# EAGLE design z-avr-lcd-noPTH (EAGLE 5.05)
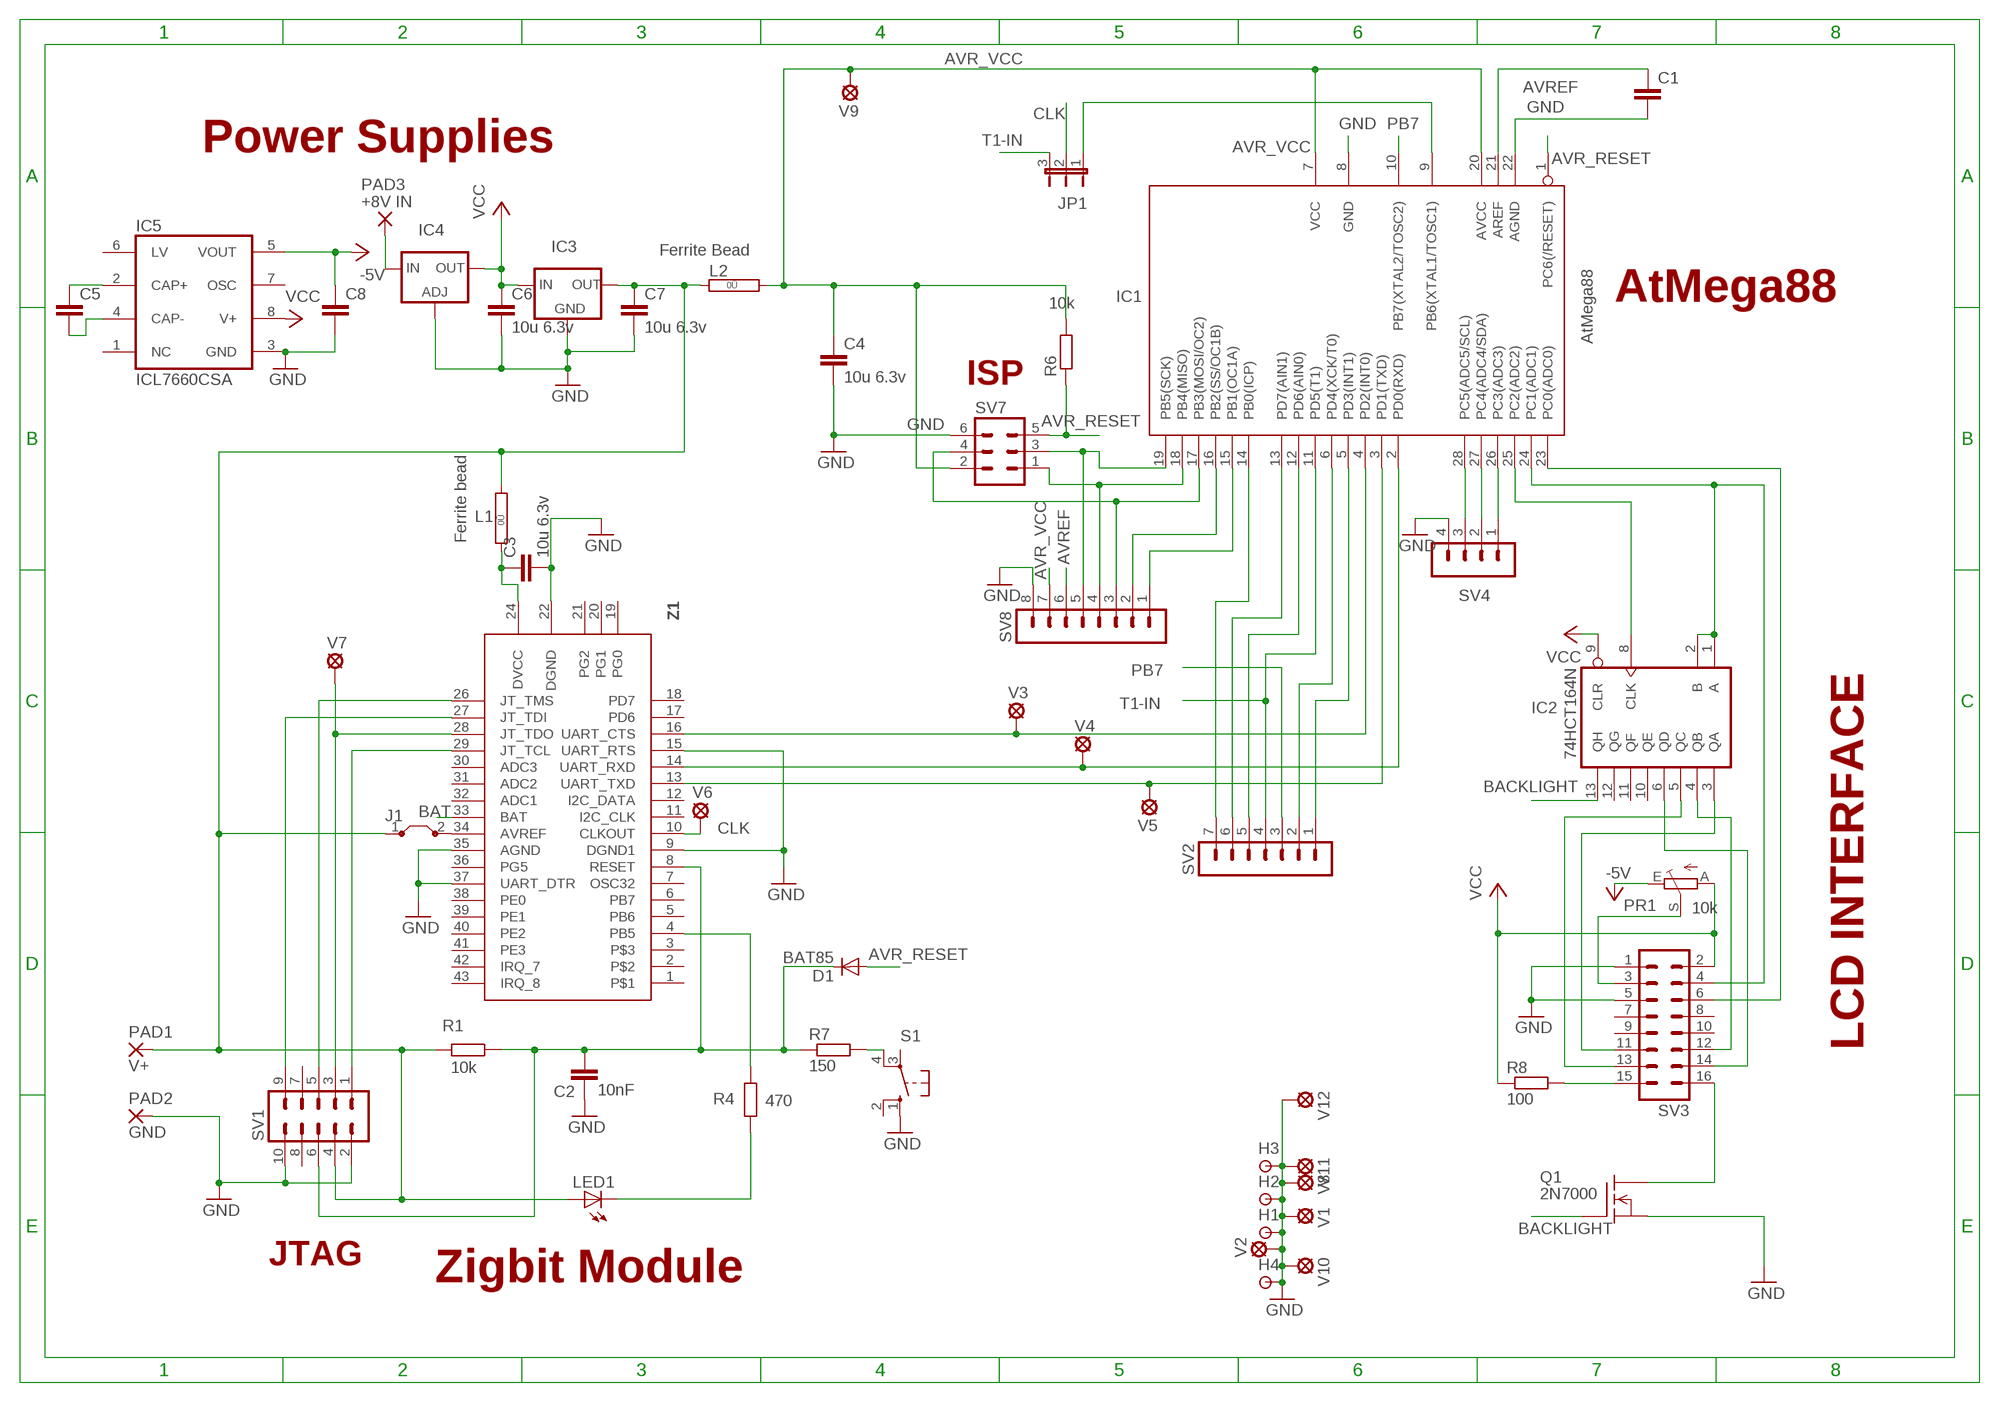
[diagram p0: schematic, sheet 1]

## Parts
C1  C-EUC1206  [C1206]
C2  10nF  C5P  [C050-030-075]
C3  10u 6.3v  C-EUC1206  [C1206]
C4  10u 6.3v  C-EUC1206  [C1206]
C5  C-EUC1206  [C1206]
C6  10u 6.3v  C-EUC1206  [C1206]
C7  10u 6.3v  C-EUC1206  [C1206]
C8  C-EUC1206  [C1206]
D1  BAT85  1N4148  [DO34-7]
H1  HOLE/SMALL  [1,6/0,8]
H2  HOLE/SMALL  [1,6/0,8]
H3  HOLE/SMALL  [1,6/0,8]
H4  HOLE/SMALL  [1,6/0,8]
IC1  AtMega88  MEGA8-P  [DIL28-3]
IC2  74HCT164N  74ACT164N  [DIL14]
IC3  MC1702-3302E/TO 3.3V LDO VREG  XC63FPT  [TO92]
IC4  LD117ADT50TR  [DPACK]
IC5  ICL7660CSA  [SO08]
J1  J7MM  [07]
JP1  3 way Jumper  JP2E  [JP2]
L1  Ferrite bead  0R  [0R/10]
L2  Ferrite Bead  JUMPER_0R  [JUMPER_0R/10]
LED1  3MM red LED  LED-3MM3MM  [HLMP-D105]
PAD1  V+  TERMINAL-PAD  [2,54/1,1]
PAD2  GND  TERMINAL-PAD  [2,54/1,1]
PAD3  +8V IN  PAD-TERMINAL  [2,54/1,1]
PR1  10k  VAR_RESISTOR_TRIMS63P  [S63P]
Q1  2N7000  [TO92]
R1  10k  R  [0207/10]
R4  470  R  [0207/10]
R6  10k  R  [0207/10]
R7  150  R  [0207/10]
R8  100  R  [0207/10]
S1  BW3-1000 PCB pushbutton  10-XX  [B3F-10XX]
SV1  10 way IDC header  ML10  [ML10]
SV2  7 way pin header  MA07-1  [MA07-1]
SV3  16 way IDC mail header  ML16  [ML16]
SV4  4 way pin header  MA04-1  [MA04-1]
SV7  6 pin IDC male header  ML6  [ML6]
SV8  8 way pin header  MA08-1  [MA08-1]
V1  HOLE/VIA  [LSP10]
V2  HOLE-VIA  [LSP10]
V3  HOLE-VIA  [LSP10]
V4  HOLE-VIA  [LSP10]
V5  HOLE-VIA  [LSP10]
V6  HOLE-VIA  [LSP10]
V7  HOLE-VIA  [LSP10]
V8  HOLE-VIA  [LSP10]
V9  HOLE-VIA  [LSP10]
V10  HOLE-VIA  [LSP10]
V11  HOLE-VIA  [LSP10]
V12  HOLE-VIA  [LSP10]
Z1  ZDM-A1281-A2N  [ZIGSMD]

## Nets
-5V: C8.1 IC5.5(VOUT) PR1.E
AVR_RESET: D1.A IC1.1(PC6(/RESET)) R6.1 SV7.5
AVR_VCC [supply]: C4.1 IC1.7(VCC) IC1.20(AVCC) L2.2 R6.2 SV7.2 SV8.7 V9.MP
AVREF: C1.1 IC1.21(AREF) SV8.6
BACKLIGHT: IC2.13(QH) Q1.2(G)
BAT: Z1.33(BAT)
CLK: JP1.2 V6.MP Z1.10(CLKOUT)
GND [supply]: C1.2 C2.1 C3.2 C4.2 C6.2 C7.2 C8.2 H1.1(P) H2.1(P) H3.1(P) H4.1(P) IC1.8(GND) IC1.22(AGND) IC3.1(GND) IC4.1(ADJ) IC5.3(GND) PAD2.1(P) Q1.3(S) S1.1(S) SV1.2 SV1.10 SV3.1 SV3.5 SV4.4 SV7.6 SV8.8 V1.MP V2.MP V8.MP V10.MP V11.MP V12.MP Z1.9(DGND1) Z1.15(UART_RTS) Z1.22(DGND) Z1.35(AGND) Z1.37(UART_DTR)
N$1: IC1.18(PB4(MISO)) SV7.1 SV8.4
N$2: IC1.19(PB5(SCK)) SV7.3 SV8.5
N$3: IC1.24(PC1(ADC1)) IC2.1(A) IC2.2(B) SV3.4
N$4: IC1.25(PC2(ADC2)) IC2.8(CLK)
N$5: IC1.28(PC5(ADC5/SCL)) SV4.3
N$6: R7.2 S1.4(P1)
N$7: IC1.27(PC4(ADC4/SDA)) SV4.2
N$8: IC1.17(PB3(MOSI/OC2)) SV7.4 SV8.3
N$9: SV1.5 Z1.26(JT_TMS)
N$10: SV1.1 Z1.29(JT_TCL)
N$11: SV1.3 V7.MP Z1.28(JT_TDO)
N$12: IC1.26(PC3(ADC3)) SV4.1
N$13: C2.2 D1.C R1.2 R7.1 SV1.6 Z1.8(RESET)
N$14: IC2.6(QD) SV3.14
N$15: IC1.23(PC0(ADC0)) SV3.6
N$16: J1.2 Z1.34(AVREF)
N$17: C5.1 IC5.2(CAP+)
N$18: IC1.4(PD2(INT0)) V3.MP Z1.16(UART_CTS)
N$19: PR1.S SV3.3
N$20: IC1.2(PD0(RXD)) V4.MP Z1.14(UART_RXD)
N$21: IC1.3(PD1(TXD)) V5.MP Z1.13(UART_TXD)
N$22: IC2.3(QA) SV3.11
N$23: IC2.4(QB) SV3.12
N$24: IC2.5(QC) SV3.13
N$25: C5.2 IC5.4(CAP-)
N$26: R8.2 SV3.15
N$27: Q1.1(D) SV3.16
N$28: R4.2 Z1.4(PB5)
N$29 [supply]: IC4.3(IN) PAD3.1(P)
N$30: LED1.K(C) R4.1
N$31: SV1.9 Z1.27(JT_TDI)
N$32: IC1.9(PB6(XTAL1/TOSC1)) JP1.1
N$33 [supply]: C3.1 L1.1 Z1.24(DVCC)
N$34 [supply]: C7.1 IC3.3(OUT) J1.1 L1.2 L2.1 LED1.A PAD1.1(P) R1.1 SV1.4
N$37: IC1.5(PD3(INT1)) SV2.1
N$38: IC1.15(PB1(OC1A)) SV8.1
N$39: IC1.16(PB2(SS/OC1B)) SV8.2
N$40: IC1.12(PD6(AIN0)) SV2.5
N$41: IC1.13(PD7(AIN1)) SV2.6
N$42: IC1.14(PB0(ICP)) SV2.7
N$44: IC1.6(PD4(XCK/T0)) SV2.2
PB7: IC1.10(PB7(XTAL2/TOSC2)) SV2.3
T1-IN: IC1.11(PD5(T1)) JP1.3 SV2.4
VCC [supply]: C6.1 IC2.9(CLR) IC3.2(IN) IC4.4(OUT) IC5.8(V+) PR1.A R8.1 SV3.2
Unconnected: IC2.10(QE) IC2.11(QF) IC2.12(QG) IC5.1(NC) IC5.6(LV) IC5.7(OSC) S1.2(S1) S1.3(P) SV1.7 SV1.8 SV3.7 SV3.8 SV3.9 SV3.10 Z1.1 Z1.2 Z1.3 Z1.5(PB6) Z1.6(PB7) Z1.7(OSC32) Z1.11(I2C_CLK) Z1.12(I2C_DATA) Z1.17(PD6) Z1.18(PD7) Z1.19(PG0) Z1.20(PG1) Z1.21(PG2) Z1.30(ADC3) Z1.31(ADC2) Z1.32(ADC1) Z1.36(PG5) Z1.38(PE0) Z1.39(PE1) Z1.40(PE2) Z1.41(PE3) Z1.42(IRQ_7) Z1.43(IRQ_8)

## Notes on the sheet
- Power Supplies
- AtMega88
- ISP
- LCD INTERFACE
- JTAG
- Zigbit Module

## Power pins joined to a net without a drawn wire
GND: IC2.7(GND)
VCC: IC2.14(VCC)

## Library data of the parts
C1 C3-C8 = rcl:C-EU: CAPACITOR, European symbol
C2 = ee2parts:C: Capacitor
D1 = ee2parts:1N4148: DIODE
H1-H4 = ee2parts:HOLE/SMALL: SMALL THROUGH-HOLE PAD/TESTPOINT
IC1 = atmel:MEGA8-P: MICROCONTROLLER 8 Kbytes FLASH, 1 kbytes SRAM, 512 bytes EEPROM, USART, 4-channel 10 bit ADC, 2-channel 8 bit ADC Pin compatible with Atmega48, ATMega88, ATMega168 Source: avr.lbr
IC2 = 74xx-eu:74*164: 8-bit parallel out SHIFT REGISTER
IC3 = v-reg:XC63FP: Positiv Voltage Regulators www.torex.co.jp/english/product/pro02/pdf/0201_xc62fp.pdf
IC4 = v-reg:LD117A?*: Low drop fixed and adjustable positive voltage regulators 1 A Source: http://www.st.com/stonline/products/literature/ds/7194/ld1117axx.pdf
IC5 = maxim:ICL7660CSA: VOLTAGE CONVERTER
J1 = jumper:J: Bridge
JP1 = jumper:JP2E: JUMPER
L1 = jumper:0R: Bridge 0R 10mm
L2 = z-avr-lcd-noPTH:JUMPER_0R: Bridge 0R 10mm
LED1 = ee2parts:LED-3MM: LED
PAD1 PAD2 = ee2parts:TERMINAL-PAD: LARGE THROUGH-HOLE PAD
PAD3 = ee2parts:PAD-TERMINAL: LARGE THROUGH-HOLE PAD
PR1 = ee2parts:VAR_RESISTOR_TRIM: Variable resistor / potentiometer Trimmer potentiometer - Note that slider to end makes variable resistance
Q1 = z-avr-lcd-noPTH:2N7000: N-Channel Enhancement MOSFET 200V; 0,16A; 11Ohm
R1 R4 R6-R8 = ee2parts:R: Resistor
S1 = switch-omron:10-XX: OMRON SWITCH
SV1 = con-harting-ml:ML10: HARTING
SV2 = con-lstb:MA07-1: PIN HEADER
SV3 = con-ml:ML16: HARTING
SV4 = con-lstb:MA04-1: PIN HEADER
SV7 = con-harting-ml:ML6: HARTING
SV8 = con-lstb:MA08-1: PIN HEADER
V1 = ee2parts:HOLE/VIA: FIXED VIA
V2-V12 = ee2parts:HOLE-VIA: FIXED VIA
Z1 = ee2parts:ZDM-A1281-A2

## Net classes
1 supply: width 0.635 mm

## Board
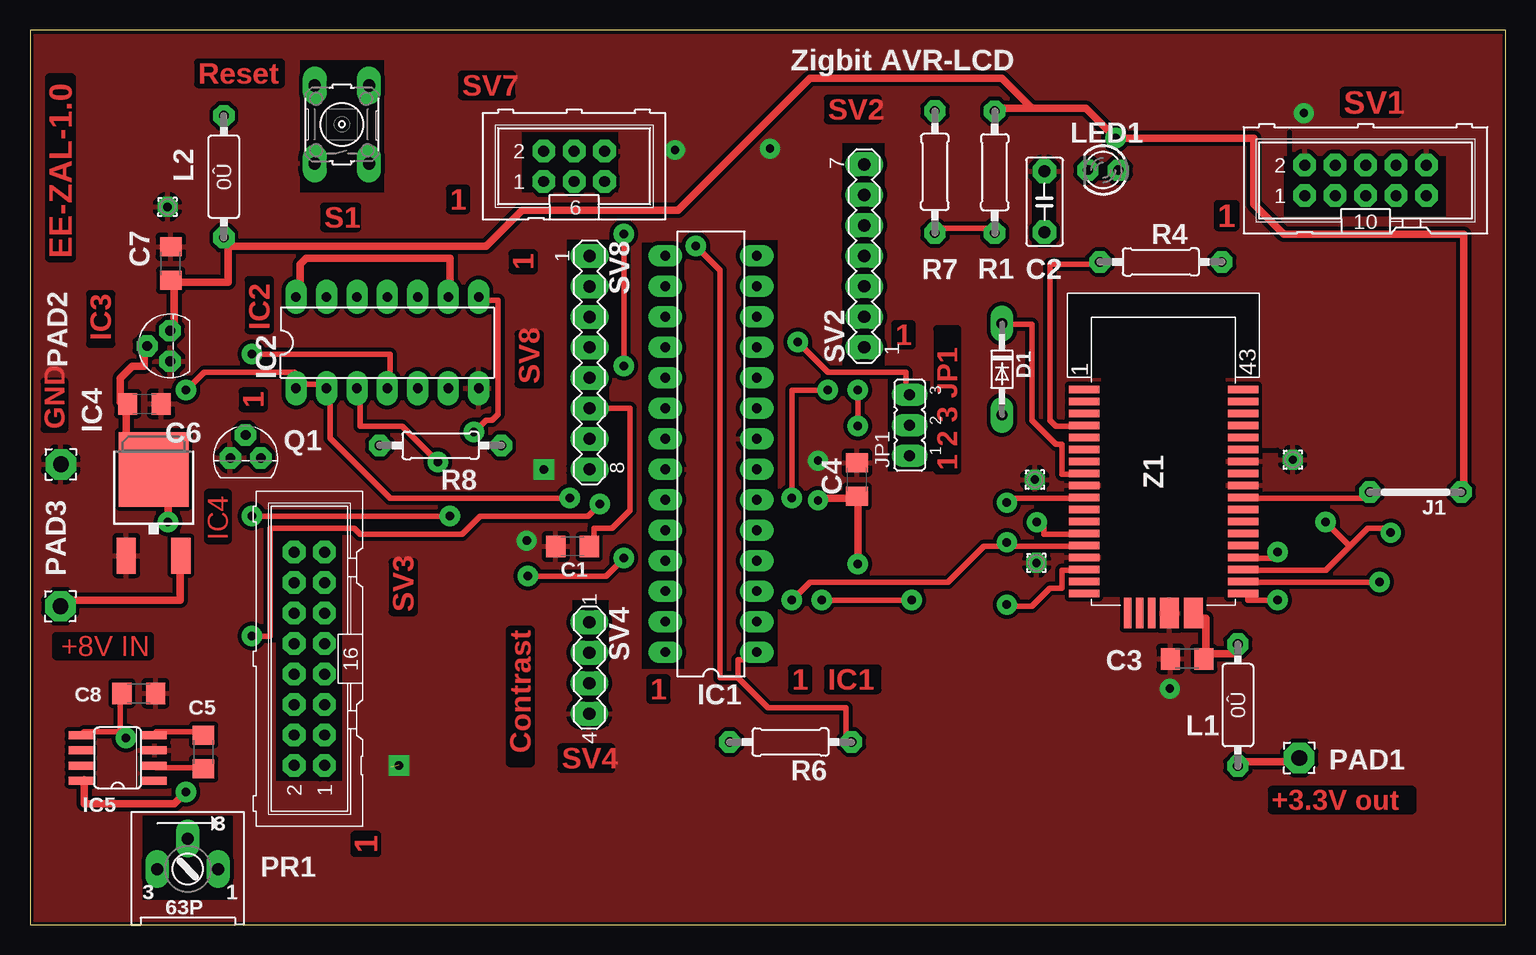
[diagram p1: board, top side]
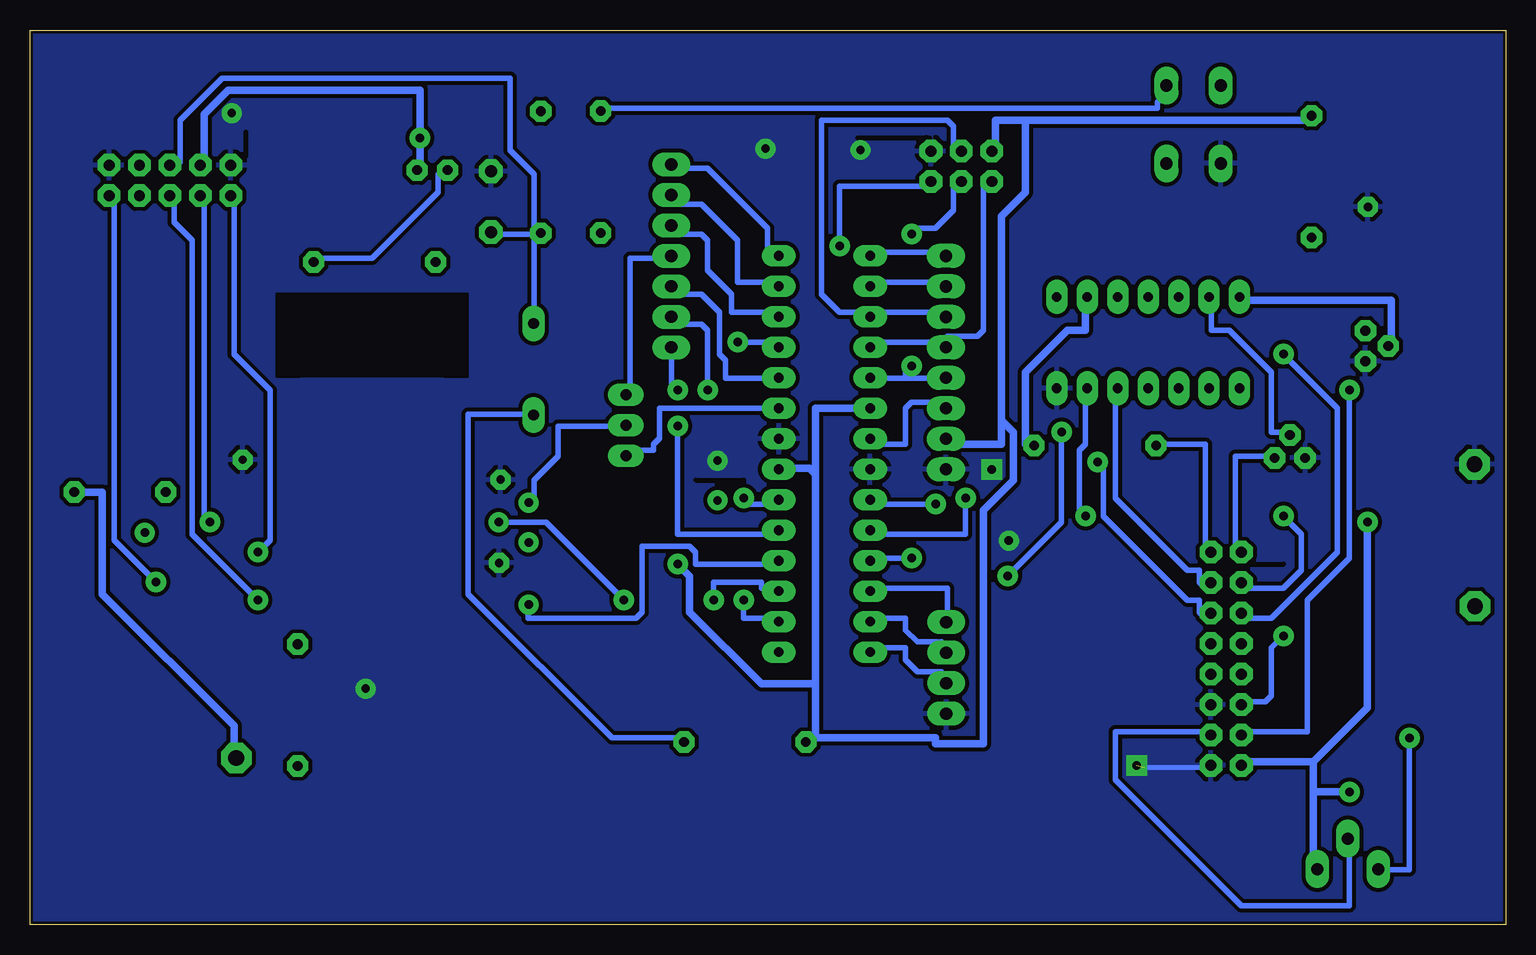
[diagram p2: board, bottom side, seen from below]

Size 123 x 74.58 mm. Coordinates in mm from the lower left corner, seen from the top.
Outline: 0,0 123,0 123,74.58 0,74.58 0,0
Copper layers (1*16): Top 0.035mm / dielectric 1.5mm / Bottom 0.035mm
Design rules "zigbit_rules *": minimum track width 18mil, minimum drill 0.7mm, track to track 13mil, track to pad 13mil, pad to pad 13mil, via to via 13mil, smd to smd 0mil, copper to edge 10mil, drill to drill 10mil, minimum pad ring 19mil, minimum via ring 20mil, stop-mask expansion 0mil, vias tented up to drill 0mil, thermal gap 15mil
tRestrict: area 104.5,59.1 to 118,64.1; area 87.2,62.1 to 91.7,63.6; area 83.5,56.6 to 85.5,63.6; area 41,61.1 to 49,66.1; area 67.7,46.7 to 71.2,65.2; area 22.5,61.1 to 29.5,72.1; area 44.8,36.6 to 48.3,57.1; area 20.5,12 to 26,32.5; area 9.4,2.1 to 16.9,9.1; area 51,21.3 to 54.5,56.8; area 59.3,21.5 to 62.3,57; area 71.5,37.8 to 75,45.3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; 2 lines
bRestrict: 4 lines
vRestrict: area 19.5,8.1 to 29,36.6; area 37,58.6 to 52.5,68.6; area 101,56.6 to 121.5,66.6; area 8.5,-0.2 to 18.7,10

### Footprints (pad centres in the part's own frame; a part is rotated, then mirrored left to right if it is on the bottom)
C1206 = smd 1.6 x 1.8: 1 -1.4,0; 2 1.4,0
C050-030-075 = drill 1 octagon: 1 -2.54,0; 2 2.54,0
DO34-7 = drill 0.9 long: A 3.81,0; C -3.81,0
1,6/0,8 = drill 0.7 pad 1.6 octagon: 1 0,0
DIL28-3 = drill 0.813 long: 1 -16.51,-3.81; 2 -13.97,-3.81; 3 -11.43,-3.81; 4 -8.89,-3.81; 5 -6.35,-3.81; 6 -3.81,-3.81; 7 -1.27,-3.81; 8 1.27,-3.81; 9 3.81,-3.81; 10 6.35,-3.81; 11 8.89,-3.81; 12 11.43,-3.81; 13 13.97,-3.81; 14 16.51,-3.81; 15 16.51,3.81; 16 13.97,3.81; 17 11.43,3.81; 18 8.89,3.81; 19 6.35,3.81; 20 3.81,3.81; 21 1.27,3.81; 22 -1.27,3.81; 23 -3.81,3.81; 24 -6.35,3.81; 25 -8.89,3.81; 26 -11.43,3.81; 27 -13.97,3.81; 28 -16.51,3.81
DIL14 = drill 0.813 long: 1 -7.62,-3.81; 2 -5.08,-3.81; 3 -2.54,-3.81; 4 0,-3.81; 5 2.54,-3.81; 6 5.08,-3.81; 7 7.62,-3.81; 8 7.62,3.81; 9 5.08,3.81; 10 2.54,3.81; 11 0,3.81; 12 -2.54,3.81; 13 -5.08,3.81; 14 -7.62,3.81
TO92 = drill 0.813 octagon: 1 -1.27,0; 2 0,1.905; 3 1.27,0
DPACK = smd 1.6 x 3: 1 -2.28,-4.8; 3 2.28,-4.8 | smd 5.8 x 6.2: 4 0,2.38
SO08 = smd 0.66 x 2.032: 1 -1.905,-3.073; 2 -0.635,-3.073; 3 0.635,-3.073; 4 1.905,-3.073; 5 1.905,3.073; 6 0.635,3.073; 7 -0.635,3.073; 8 -1.905,3.073
07 = drill 0.813 pad 1.6 octagon: 1 -3.81,0; 2 3.81,0
JP2 = drill 0.914 long: 1 -2.54,0; 2 0,0; 3 2.54,0
0R/10 = drill 0.813 pad 1.6 octagon: 1 -5.08,0; 2 5.08,0
JUMPER_0R/10 = drill 0.813 pad 1.6 octagon: 1 -5.08,0; 2 5.08,0
HLMP-D105 = drill 0.8 octagon: A -1.27,0; K 1.27,0
2,54/1,1 = drill 1.3 pad 2.54 octagon: 1 0,0
S63P = drill 1 long: A 2.54,0; E -2.54,0; S 0,2.54
TO92' = drill 0.813 octagon: 1 1.27,0; 2 0,1.905; 3 -1.27,0
0207/10 = drill 0.8 octagon: 1 -5.08,0; 2 5.08,0
B3F-10XX = drill 1.016 long: 1 -3.251,2.261; 2 3.251,2.261; 3 -3.251,-2.261; 4 3.251,-2.261
ML10 = drill 0.914 octagon: 1 -5.08,-1.27; 2 -5.08,1.27; 3 -2.54,-1.27; 4 -2.54,1.27; 5 0,-1.27; 6 0,1.27; 7 2.54,-1.27; 8 2.54,1.27; 9 5.08,-1.27; 10 5.08,1.27
MA07-1 = drill 1.016 long: 1 -7.62,0; 2 -5.08,0; 3 -2.54,0; 4 0,0; 5 2.54,0; 6 5.08,0; 7 7.62,0
ML16 = drill 0.914 octagon: 1 -8.89,-1.27; 2 -8.89,1.27; 3 -6.35,-1.27; 4 -6.35,1.27; 5 -3.81,-1.27; 6 -3.81,1.27; 7 -1.27,-1.27; 8 -1.27,1.27; 9 1.27,-1.27; 10 1.27,1.27; 11 3.81,-1.27; 12 3.81,1.27; 13 6.35,-1.27; 14 6.35,1.27; 15 8.89,-1.27; 16 8.89,1.27
MA04-1 = drill 1.016 long: 1 -3.81,0; 2 -1.27,0; 3 1.27,0; 4 3.81,0
ML6 = drill 0.914 octagon: 1 -2.54,-1.27; 2 -2.54,1.27; 3 0,-1.27; 4 0,1.27; 5 2.54,-1.27; 6 2.54,1.27
MA08-1 = drill 1.016 long: 1 -8.89,0; 2 -6.35,0; 3 -3.81,0; 4 -1.27,0; 5 1.27,0; 6 3.81,0; 7 6.35,0; 8 8.89,0
LSP10 = drill 0.7 pad 1.016 round: MP 0,0
ZIGSMD = smd 0.635 x 2.54: 1 7,6.635; 2 6,6.635; 3 5,6.635; 4 4,6.635; 5 3,6.635; 6 2,6.635; 7 1,6.635; 8 0,6.635; 9 -1,6.635; 10 -2,6.635; 11 -3,6.635; 12 -4,6.635; 13 -5,6.635; 14 -6,6.635; 15 -7,6.635; 16 -8,6.635; 17 -9,6.635; 18 -10,6.635; 26 -10,-6.635; 27 -9,-6.635; 28 -8,-6.635; 29 -7,-6.635; 30 -6,-6.635; 31 -5,-6.635; 32 -4,-6.635; 33 -3,-6.635; 34 -2,-6.635; 35 -1,-6.635; 36 0,-6.635; 37 1,-6.635; 38 2,-6.635; 39 3,-6.635; 40 4,-6.635; 41 5,-6.635; 42 6,-6.635; 43 7,-6.635 | smd 2.54 x 0.635: 19 -11.635,3; 20 -11.635,2; 21 -11.635,1 | smd 2.54 x 1.6: 22 -11.635,-0.5; 24 -11.635,-2.5

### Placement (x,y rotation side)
C1  45.23,31.54 180 top
C2  84.57,60.27 270 top
C3  96.46,22.17 180 top
C4  68.94,37.12 90 top
C5  14.47,14.42 90 top
C6  9.54,43.42 0 top
C7  11.74,55.12 90 top
C8  9.07,19.3 0 top
D1  81.03,46.31 270 top
H1  105.27,38.77 0 top
H2  11.47,59.84 0 top
H3  83.77,37.11 0 top
H4  83.9,30.17 0 top
IC1  56.77,39.25 90 top
IC2  29.79,48.53 0 top
IC3  11.68,48.25 90 top
IC4  10.31,35.58 0 top
IC5  7.31,13.92 90 top
J1  115.5,36.08 180 top
JP1  73.32,41.65 90 top
L1  100.69,18.32 270 top
L2  16.16,62.36 90 top
LED1  89.46,62.9 180 top
PAD1  105.81,13.92 0 top
PAD2  2.58,38.39 90 top
PAD3  2.54,26.56 0 top
PR1  13.15,4.66 0 top
Q1  2N7000  [TO92']  17.97,38.92 0 top
R1  80.42,62.73 270 top
R4  94.27,55.25 180 top
R6  63.4,15.24 180 top
R7  75.43,62.75 90 top
R8  34.22,39.96 180 top
S1  26,66.71 90 top
SV1  111.34,62.05 0 top
SV2  69.55,55.75 90 top
SV3  23.29,22.18 90 top
SV4  46.62,21.42 270 top
SV7  45.36,63.23 0 top
SV8  46.64,46.86 270 top
V1  53.77,64.58 0 top
V2  95.02,19.69 0 top
V3  81.43,26.69 0 top
V4  81.43,31.88 0 top
V5  83.93,33.57 0 top
V6  81.43,35.19 0 top
V7  113.43,32.69 0 top
V8  65.69,38.69 0 top
V9  65.69,35.38 0 top
V10  61.69,64.69 0 top
V11  106.19,67.65 0 top
V12  41.41,32.03 0 top
Z1  94.49,37.62 90 top

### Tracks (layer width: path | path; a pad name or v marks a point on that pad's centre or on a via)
-5V  (via drill 0.7)
  Top 0.457: 7.5,16.08 7.5,19.08 C8.1 | 7.5,16.08 4.5,16.08 IC5.5 | 7.5,16.08 v8,15.58
  Bottom 0.457: v8,15.58 8,4.58 10.5,4.58 PR1.E
AVR_RESET  (via drill 0.7)
  Top 0.457: 59,20.58 61.5,18.08 68,18.08 68,15.58 R6.1 | 59,20.58 59,22.08 59.5,22.08 IC1.1 | v55.5,56.58 57.5,54.58 57.5,20.58 59,20.58
  Bottom 0.457: D1.A 81.5,42.58 86.5,42.58 86.5,27.58 74.5,15.58 68.5,15.58 R6.1 | v55.5,56.58 55.5,61.58 48,61.58 SV7.5
AVR_VCC  (via drill 0.7)
  Top 0.635: V9.MP 66,35.58 68.5,35.58 C4.1 69,35.58 v69,30.08
  Bottom 0.635: 57.5,15.58 58,15.58 R6.2 57.5,15.58 | 57.5,20.08 57.5,37.58 | 57.5,15.58 57.5,20.08 | 57.5,37.58 58,38.08 60.5,38.08 IC1.7 | 57.5,37.58 57.5,43.08 53,43.08 IC1.20 | v69,30.08 68,29.08 68,26.08 62,20.08 57.5,20.08 | 40,67.08 42.5,67.08 42.5,64.58 SV7.2 | 40,67.08 16.5,67.08 L2.2 | 42,42.08 42,59.08 40,61.08 40,67.08 | 42,42.08 42,40.08 46.5,40.08 SV8.7 | 57.5,15.58 47.5,15.58 47.5,15.08 43.5,15.08 43.5,34.58 41,37.08 41,41.08 42,42.08
AVREF
  Top 0.457: C1.1 47,31.58 47,33.08 48.5,33.08 50,34.58 50,43.08 48,43.08 SV8.6
  Bottom 0.457: IC1.21 52.5,40.08 50,40.08 50,43.08 49.5,43.58 47,43.58 47,43.08 SV8.6
BACKLIGHT
  Bottom 0.457: Q1.2 18,41.08 19.5,41.08 19.5,46.08 23,49.58 24.5,49.58 24.5,52.08 IC2.13
CLK
  Top 0.457: Z1.10 87.5,35.58 81.5,35.58 V6.MP
  Bottom 0.457: JP1.2 73.5,41.58 79,41.58 79,39.08 81,37.08 81,35.58 V6.MP
GND  (via drill 0.7)  (1 unrouted)
  Bottom 0.406: 25.32,13.23 25.39,13.16 30.11,13.16
  other vias: 42.83,37.94 30.75,13.3
  pour Bottom: 0,74.08 123,74.08 123,0 0,0
  pour Top: 0,74.08 123,74.08 123,0 0,0
N$1
  Bottom 0.457: IC1.18 52.5,48.58 47,48.58 SV8.4 46.5,48.58 46.5,49.08 44,49.08 43.5,49.58 43.5,61.58 43,61.58 SV7.1
N$2  (via drill 0.7)
  Top 0.457: v49.5,46.58 v49.5,57.58
  Bottom 0.457: 50,45.58 47,45.58 SV8.5 | 50,45.58 52.5,45.58 IC1.19 | v49.5,57.58 49.5,58.08 47.5,58.08 46,59.58 46,61.58 45.5,61.58 SV7.3 | v49.5,46.58 50,46.08 50,45.58
N$3  (via drill 0.7)
  Top 0.457: 23,45.08 24.5,45.08 IC2.2 25,44.58 25,40.58 30,35.58 v45,35.58 | 23,45.08 22.5,45.08 IC2.1 23,45.08 | v13,44.58 14.5,46.08 22,46.08 23,45.08
  Bottom 0.457: v45,35.58 45,32.58 52.5,32.58 IC1.24 | v13,44.58 13,30.58 16.5,27.08 16.5,16.08 22,16.08 SV3.4
N$4  (via drill 0.7)
  Top 0.457: v49.5,30.58 48,29.08 v41.5,29.08 | v37,41.08 38,42.08 38.5,42.08 39,42.58 39,52.08 37.5,52.08 IC2.8
  Bottom 0.457: v49.5,30.58 52.5,30.58 IC1.25 | v41.5,29.08 37,33.58 v37,41.08
N$5
  Bottom 0.457: IC1.28 52.5,23.08 50,23.08 50,22.08 49,21.08 47,21.08 47,20.58 SV4.3
N$6
  Bottom 0.457: R7.2 75,68.08 29,68.08 29,68.58 28.5,69.08 28.5,69.58 S1.4
N$7
  Bottom 0.457: IC1.27 52.5,25.58 50,25.58 50,24.58 49,23.58 47,23.58 47,23.08 SV4.2
N$8
  Bottom 0.457: SV8.3 47,51.08 52.5,51.08 IC1.17 53,51.08 55.5,51.08 57,52.58 57,67.08 46.5,67.08 46,66.58 46,65.08 45.5,64.58 SV7.4
N$9  (via drill 0.7)
  Top 0.457: v104,27.08 101.5,27.08 101.5,27.58 Z1.26
  Bottom 0.457: v104,27.08 109.5,32.58 109.5,57.08 111,58.58 111,60.58 SV1.5
N$10  (via drill 0.7)
  Top 0.457: v104,31.08 103.5,30.58 101.5,30.58 Z1.29
  Bottom 0.457: v104,31.08 103,32.08 103,44.58 106,47.58 106,60.58 SV1.1
N$11  (via drill 0.7)
  Top 0.457: 110,31.58 111.5,33.08 113,33.08 V7.MP | 110,31.58 108,29.58 101.5,29.58 Z1.28 | 110,31.58 v108,33.58
  Bottom 0.457: v108,33.58 108.5,34.08 108.5,60.58 SV1.3
N$12
  Bottom 0.457: IC1.26 52.5,28.08 46.5,28.08 46.5,25.58 SV4.1
N$13
  Top 0.457: Z1.8 87.5,37.58 86,37.58 86,40.08 85.5,40.08 83.5,42.08 83.5,50.08 81.5,50.08 D1.C | R7.1 75.5,58.08 80,58.08 R1.2
  Bottom 0.457: 81,57.58 84.5,57.58 C2.2 | 81,57.58 80.5,57.58 R1.2 81,57.58 | 81,57.58 81,62.58 83,64.58 83,70.58 107,70.58 110.5,67.08 110.5,63.58 111,63.58 SV1.6 | 81,57.58 81,50.58 D1.C
N$14  (via drill 0.7)
  Top 0.457: v35,34.08 v18.5,34.08
  Bottom 0.457: v35,34.08 35.5,34.58 35.5,39.58 35,40.08 35,44.58 IC2.6 | v18.5,34.08 17,32.58 17,29.58 18.5,28.08 22,28.08 SV3.14
N$15  (via drill 0.7)
  Top 0.457: v47.5,35.08 46.5,34.08 37.5,34.08 36,32.58 27.5,32.58 27,33.08 20,33.08 20,24.08 v18.5,24.08
  Bottom 0.457: v47.5,35.08 52.5,35.08 IC1.23 | v18.5,24.08 19.5,23.08 19.5,19.08 20,18.58 22,18.58 SV3.6
N$16
  Top 0.457: Z1.34 101.5,35.58 111.5,35.58 112,36.08 J1.2
N$17
  Top 0.457: C5.1 14,13.08 10.5,13.08 IC5.2
N$18
  Top 0.457: Z1.16 87.5,29.58 86,29.58 86,28.08 85,28.08 83.5,26.58 81.5,26.58 V3.MP
  Bottom 0.457: IC1.4 61,30.08 67.5,30.08 67.5,31.08 68,31.58 72,31.58 72,26.08 72.5,25.58 81.5,25.58 81.5,26.58 V3.MP
N$19
  Bottom 0.457: SV3.3 25,16.08 32.5,16.08 32.5,12.08 22,1.58 13,1.58 13,7.08 PR1.S
N$20  (via drill 0.7)
  Top 0.457: Z1.14 87.5,31.58 81.5,31.58 V4.MP 81,31.58 79.5,31.58 76.5,28.58 65,28.58 v63.5,27.08
  Bottom 0.457: v63.5,27.08 63.5,25.58 61,25.58 IC1.2
N$21  (via drill 0.7)
  Top 0.457: Z1.13 87.5,32.58 84.5,32.58 84.5,33.58 84,33.58 V5.MP | v66,27.08 v73.5,27.08
  Bottom 0.457: v66,27.08 66,28.58 62,28.58 62,28.08 61,28.08 IC1.3 | v73.5,27.08 80,33.58 83.5,33.58 V5.MP
N$22  (via drill 0.7)
  Top 0.457: v34,38.58 31,41.58 27.5,41.58 27.5,44.58 IC2.3
  Bottom 0.457: v34,38.58 33.5,38.08 33.5,34.08 26.5,27.08 25.5,27.08 25.5,26.08 25,25.58 SV3.11
N$23  (via drill 0.7)
  Top 0.457: v18.5,47.58 30,47.58 30,45.08 IC2.4
  Bottom 0.457: v18.5,47.58 14,43.08 14,31.08 19.5,25.58 22,25.58 SV3.12
N$24
  Bottom 0.457: IC2.5 32.5,44.58 32.5,35.58 26.5,29.58 25.5,29.58 25.5,28.58 25,28.08 SV3.13
N$25
  Top 0.457: C5.2 14,16.08 10.5,16.08 IC5.4
N$26
  Bottom 0.457: R8.2 29,40.08 25,40.08 25,31.08 SV3.15
N$27
  Bottom 0.457: Q1.1 19.5,39.08 22.5,39.08 22.5,31.08 SV3.16
N$28
  Top 0.457: Z1.4 87.5,41.58 85.5,41.58 85,42.08 85,55.08 89,55.08 R4.2
N$29
  Top 0.635: IC4.3 12.5,30.58 12.5,27.08 3,27.08 2.5,26.58 PAD3.1
N$30
  Bottom 0.457: LED1.K 88.5,62.58 89,62.58 89,61.08 94.5,55.58 99,55.58 R4.1
N$31  (via drill 0.7)
  Top 0.457: v112.5,28.58 101.5,28.58 Z1.27
  Bottom 0.457: v112.5,28.58 116,32.08 116,60.58 SV1.9
N$32
  Bottom 0.457: IC1.9 61,43.08 70.5,43.08 70.5,40.58 71,40.08 71,39.58 73,39.58 JP1.1
N$33
  Top 0.635: 98,22.58 98,25.58 97,25.58 Z1.24 | 98,22.58 100.5,22.58 100.5,23.08 L1.1 | C3.1 98,22.58
N$34  (via drill 0.7)
  Top 0.635: L1.2 101,13.58 105.5,13.58 PAD1.1 | 12,53.58 12,49.58 IC3.3 | 16.5,56.58 16.5,53.58 12,53.58 | 16.5,56.58 16.5,57.08 L2.1 16.5,56.58 | 12,53.58 C7.1 | 83.5,68.08 80.5,68.08 R1.1 | 83.5,68.08 88,68.08 v90.5,65.58 102,65.58 102,60.08 104.5,57.58 119.5,57.58 119.5,36.08 J1.1 | 16.5,56.58 38,56.58 41,59.58 54,59.58 65,70.58 81,70.58 83.5,68.08
  Bottom 0.635: J1.1 117,36.08 117,27.58 106,16.58 106,14.08 PAD1.1 | LED1.A 90.5,63.08 v90.5,65.58 90.5,69.58 106.5,69.58 108.5,67.58 108.5,63.58 SV1.4
N$37  (via drill 0.7)
  Top 0.457: v69,41.58 v69,44.58
  Bottom 0.457: v69,41.58 69,32.58 61,32.58 IC1.5 | v69,44.58 69.5,45.08 69.5,48.08 SV2.1
N$38
  Bottom 0.457: IC1.15 52.5,56.08 47,56.08 SV8.1
N$39
  Bottom 0.457: IC1.16 52.5,53.58 47,53.58 SV8.2
N$40
  Bottom 0.457: IC1.12 61,51.08 64.5,51.08 64.5,52.58 66.5,54.58 66.5,57.08 67,57.58 69.5,57.58 69.5,58.08 SV2.5
N$41
  Bottom 0.457: IC1.13 61,53.58 64,53.58 64,57.08 67,60.08 69.5,60.08 69.5,60.58 SV2.6
N$42
  Bottom 0.457: IC1.14 61,56.08 61.5,56.58 61.5,58.08 66.5,63.08 69.5,63.08 SV2.7
N$44  (via drill 0.7)
  Top 0.457: v63.5,35.58 63.5,44.58 v66.5,44.58
  Bottom 0.457: v63.5,35.58 63.5,35.08 61,35.08 IC1.6 | v66.5,44.58 66.5,49.58 67,50.08 69.5,50.08 69.5,50.58 SV2.2
PB7
  Bottom 0.457: IC1.10 61,45.58 65,45.58 65,47.08 65.5,47.58 65.5,51.08 67,52.58 69.5,52.58 69.5,53.08 SV2.3
T1-IN  (via drill 0.7)
  Top 0.457: v64,48.58 66.5,46.08 73,46.08 73,45.08 JP1.3
  Bottom 0.457: v64,48.58 61,48.58 IC1.11 | SV2.4 70,55.58 73,55.58 73,44.58 JP1.3
VCC  (via drill 0.7)
  Top 0.635: v13,11.08 12,10.08 4.5,10.08 4.5,12.08 IC5.8 | IC3.2 9.5,48.08 9.5,46.58 8.5,46.58 7.5,45.58 7.5,43.58 8,43.58 C6.1 8,43.08 8,38.08 10,38.08 IC4.4 10.5,37.58 11.5,37.58 v11.5,33.58 | IC2.9 35,52.58 35,55.58 23,55.58 22.5,55.08 22.5,52.58 IC2.14
  Bottom 0.635: 16,11.08 v13,11.08 | 16,11.08 16,5.08 PR1.A | 16,13.58 22,13.58 SV3.2 | 16,13.58 16,11.08 | R8.1 39.5,40.08 40,40.08 40,46.08 36.5,49.58 35,49.58 35,52.08 IC2.9 | IC2.14 22,52.08 9.5,52.08 9.5,48.58 IC3.2 | 16,13.58 11.5,18.08 v11.5,33.58

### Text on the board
Top: Reset | SV7 | SV2 | 1 | 1 | S1 | EE-ZAL-1.0 | 1 | IC3 | 1 | IC2 | SV8 | 1 | 1 2 3 JP1 | IC4 | SV3 | Contrast | +8V IN | 1 | 1 | IC1 | SV4 | +3.3V out | 1
tPlace: Zigbit AVR-LCD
